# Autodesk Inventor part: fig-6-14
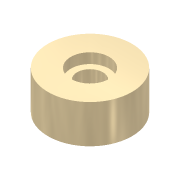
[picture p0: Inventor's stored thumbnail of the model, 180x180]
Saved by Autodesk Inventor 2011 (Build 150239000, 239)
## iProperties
Shininess: 65.0
Angle Display Precision: 2
Document Length Units: 11269
Document Angle Units: 11279
Document Time Units: 11290
Document Mass Units: 11283
Document Length Units Precision: 3
Document Angle Units Precision: 2
Created: 2001-11
Part Number: fig-6-14
Document SubType Name: Modeling
Designer: Renu Muthoo
Density: 1 g/cm^3
Density: 0.0
Volumn: 0.0
Area: 0.0
PropertySet Name: Model Information
Control State: 0
Master: False
Checked Out: False
Author: Renu Muthoo
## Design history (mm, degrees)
sketch "Sketch1"
  geometry: C1 r 16.401 at (0, 0)
  constraints: 1 centre point
extrude "Extrusion1" new body sketch "Sketch1" distance "d0" = 15; taper "d1" = 0 deg
hole "Hole3" diameter "d18" = 10.106; stored, may be unused: countersink angle "d22" = 90 deg, drill point angle "d24" = 118 deg; dims "d16" = 10, "d17" = 10, "d19" = 6, "d20" = 15, "d21" = 4, "d23" = 10
body "Solid1"
